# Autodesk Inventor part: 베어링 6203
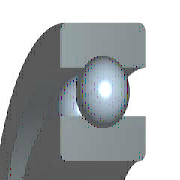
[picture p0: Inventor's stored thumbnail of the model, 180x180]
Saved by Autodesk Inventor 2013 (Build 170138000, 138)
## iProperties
IsCustomPart: 0
Company: 한국ATC센터
Created: 2014-08
Part Number: 베어링 6203
Material: 강, 연강
Description: 깊은 그루브 볼 베어링
Document SubType Name: Modeling
Standard: KS B 2023
Designer: KYOUNG IL JANG
Standards Organization: KS
Language: ko-KR
Size Designation: 6203 - 17 x 40 x 12
Categories: <MemberInstance><Categories><Category DisplayName="샤프트 부품" InternalName="7f7aeb1f-a693-4053-b835-cee3144e0d98" Mnemonic="SHFT"><Category DisplayName="베어링" Inter
Density: 7.86 g/cm^3
Mass: 64.9809 g
Surface Area: 64.3582 cm^2
Volume: 8.26729 cm^3
Author: KYOUNG IL JANG
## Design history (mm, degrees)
sketch "스케치" dims "d0" = 5.98 (= -0.26 x WD + 0.26 x BD)
  geometry: L1 (3.01, 14.25)-(8.99, 14.25); L2 (6, 14.25)-(6, 11.26); L3 (6, 14.25)-(6, 17.24); L4 (3.778, 12.249)-(0, 12.249); L5 (0, 8.5)-(12, 8.5); L6 (3.778, 16.251)-(0, 16.251); L7 (0, 20)-(12, 20); L8 (12, 8.5)-(12, 12.249); L9 (8.222, 12.249)-(12, 12.249); L10 (8.222, 16.251)-(12, 16.251); L11 (12, 20)-(12, 16.251); L12 (-1.4, 0)-(8.4, 0) reference; L13 (0, -0.3)-(0, 5.3) reference
  constraints: 22 end point, 4 point on line, 2 collinear, 2 perpendicular, 2 symmetric about line, 1 midpoint, 1 parallel, 14 other
  dimensions: "d9" = 17 diameter of L5 L12 (= WD); "d11" = 40 diameter of L7 L12 (= BD); "d12" = 12 distance between parallel lines of L8 L13 (= KB); "d13" = 24.498 diameter of L9 L12 (= 0.326 x BD + 0.674 x WD)
revolve "본체" stored, may be unused: angle "d6" = 90 deg
revolve "볼" stored, may be unused: angle "d7" = 90 deg
pattern_circular "IDS_ARRAYBALL[SIMPL:T]" dims angle "d3" = 360 deg
body "Solid1"
fillet "모깎기1" dims "d1" = 0.6 (= KRS)
other parameters: "WD" = 17 [user parameter; used in 5 equation terms], "BD" = 40 [user parameter; used in 5 equation terms], "KB" = 12 [user parameter; used in 1 equation term], "KRS" = 0.6 [user parameter; used in 1 equation term], "d4" = 0, "d5" = 0, "d8" = 0, "d14" = 0, "d15" = 0, "BBA" = 0 [user parameter], "BC0" = 4750000 [user parameter], "BC" = 9560000 [user parameter], "WR" = 8.5 (= 0.5 x WD) [user parameter]
